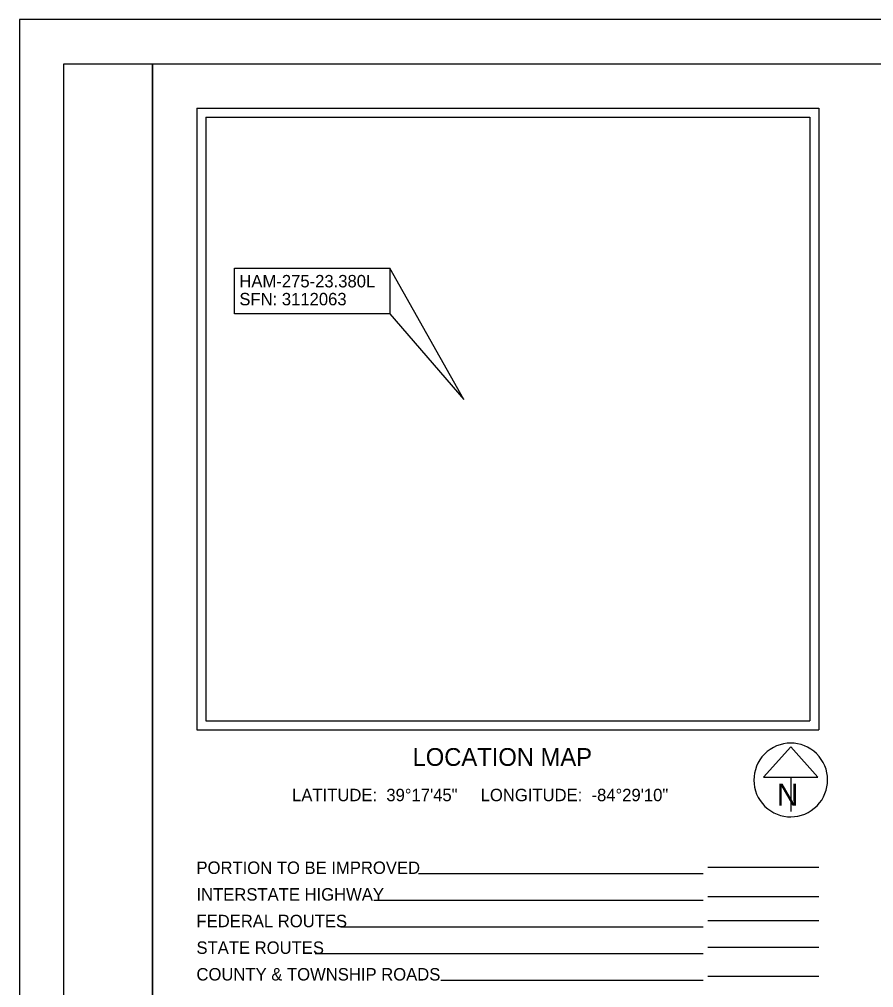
# Model space of a CAD drawing. Extents: x 0 to 34, y -6.8 to 22.
# Drawn here: x 0 to 9.62, y 11.1 to 22 of the extents above; entities that cross this region are included whole.
import ezdxf

# ---------------------------------------------------------------- set-up
doc = ezdxf.new("R2010")
doc.units = 0
for name, color, linetype in [('GM_X_County', 7, 'Continuous'), ('GM_X_Minor_Lake', 7, 'Continuous'), ('GM_X_Minor_Lake_Text', 7, 'Continuous'), ('GM_X_Minor_River', 7, 'Continuous'), ('GM_X_Minor_River_Text', 7, 'Continuous')]:
    doc.layers.add(name, color=color, linetype=linetype)

msp = doc.modelspace()

# ---------------------------------------------------------------- linework, layer by layer
at = {"layer": 'GM_X_County'}
msp.add_lwpolyline([(0, 0), (34, 0), (34, 22), (0, 22)], close=True, dxfattribs=at)
at = {"layer": 'GM_X_Minor_Lake'}
msp.add_lwpolyline([(2.422, 19.198), (4.173, 19.198), (4.173, 18.684), (2.422, 18.684)], close=True, dxfattribs=at)
at = {"layer": 'GM_X_Minor_Lake_Text'}
for p, q in [((2, 21), (9, 21)), ((2, 21), (2, 14)), ((9, 21), (9, 14)), ((2.1, 20.9), (2.1, 14.1)), ((2.1, 20.9), (8.9, 20.9)), ((8.9, 20.9), (8.9, 14.1)), ((2.1, 14.1), (8.9, 14.1)), ((2.1, 14.1), (2.1, 14.1)), ((2, 14), (9, 14)), ((8.685, 13.809), (8.377, 13.468)), ((8.992, 13.468), (8.685, 13.809)), ((8.377, 13.468), (8.992, 13.468)), ((8.685, 13.468), (8.685, 13.081)), ((8.685, 13.435), (8.685, 13.435)), ((8.685, 13.435), (8.685, 13.435)), ((7.75, 12.455), (9, 12.455)), ((7.7, 12.377), (4.494, 12.377)), ((9, 12.121), (7.75, 12.121)), ((7.7, 12.077), (3.99, 12.077)), ((7.7, 11.777), (3.619, 11.777)), ((9, 11.849), (7.75, 11.849)), ((7.7, 11.477), (3.329, 11.477)), ((9, 11.549), (7.75, 11.549)), ((7.7, 11.177), (4.745, 11.177)), ((9, 11.222), (7.75, 11.222))]:
    msp.add_line(p, q, dxfattribs=at)
msp.add_arc((8.685, 13.435), 0.415, 129.7798, 129.7633, dxfattribs=at)
at = {"layer": 'GM_X_Minor_River'}
msp.add_lwpolyline([(5.005, 17.72), (4.173, 19.198), (4.173, 18.684)], close=True, dxfattribs=at)
at = {"layer": 'GM_X_Minor_River_Text'}
for points in [[(0.5, 21.5), (1.5, 21.5), (1.5, 0.5), (0.5, 0.5)], [(1.5, 21.5), (33.5, 21.5), (33.5, 0.5), (1.5, 0.5)]]:
    msp.add_lwpolyline(points, close=True, dxfattribs=at)

# ---------------------------------------------------------------- texts
at = {"layer": 'GM_X_Minor_Lake'}
for s, height, p in [('HAM-275-23.380L', 0.14, (2.477, 18.982)), ('SFN: 3112063', 0.14, (2.477, 18.78)), ('LOCATION MAP', 0.2, (4.427, 13.594)), ('LATITUDE:  39°17\'45"     LONGITUDE:  -84°29\'10"', 0.14, (3.071, 13.196)), ('PORTION TO BE IMPROVED', 0.14, (1.994, 12.377)), ('INTERSTATE HIGHWAY', 0.14, (1.994, 12.077)), ('FEDERAL ROUTES', 0.14, (1.994, 11.777)), ('STATE ROUTES', 0.14, (1.994, 11.477)), ('COUNTY & TOWNSHIP ROADS', 0.14, (1.994, 11.177))]:
    msp.add_text(s, height=height, dxfattribs=at).set_placement(p)
at = {"layer": 'GM_X_Minor_Lake_Text'}
msp.add_text('N', height=0.25, dxfattribs=at).set_placement((8.529, 13.144))

doc.saveas('drawing.dxf')
